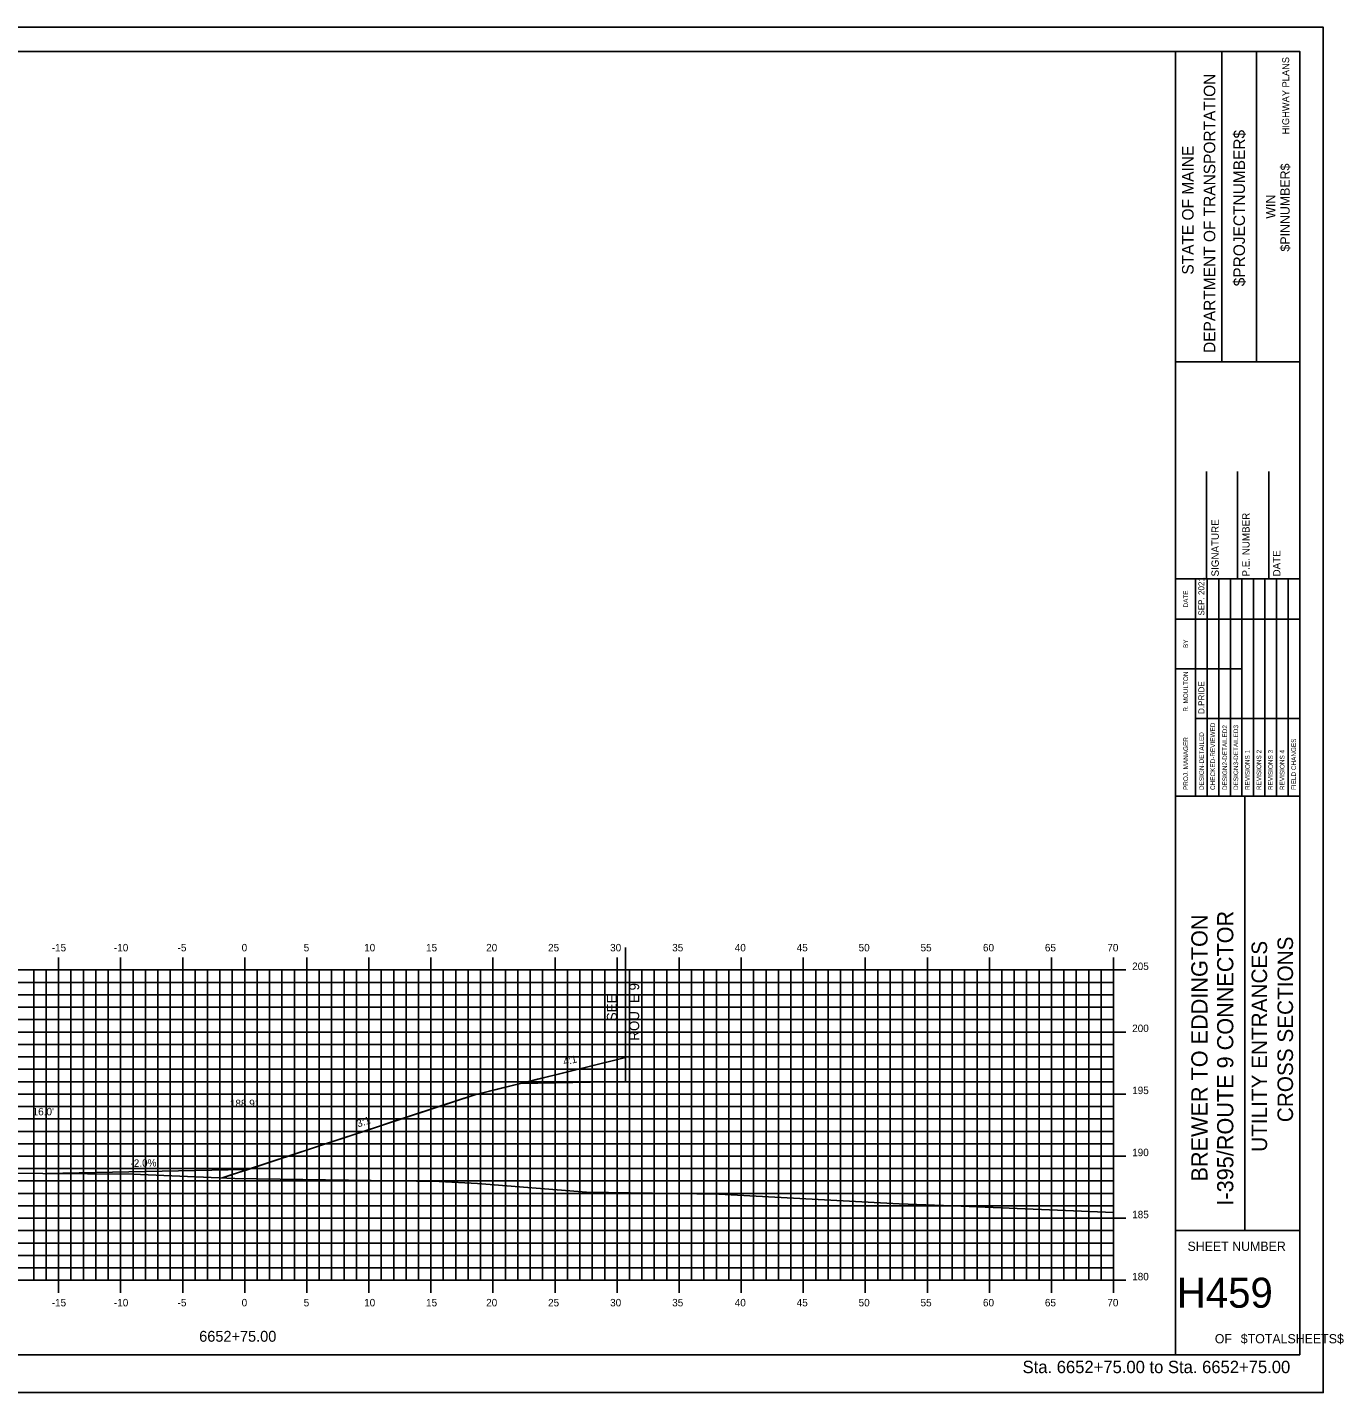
# Model space of a CAD drawing. Extents: x 1724208 to 1724380, y 458501 to 458611.
# Drawn here: x 1724273.5 to 1724379.6, y 458501.2 to 458611.2 of the extents above; entities that cross this region are included whole.
import ezdxf

# ---------------------------------------------------------------- set-up
doc = ezdxf.new("R2010")
doc.units = 0
for name, color, linetype in [('ANNOTATION', 7, 'Continuous'), ('BORDER', 7, 'Continuous'), ('D_Roadway_Centerline', 7, 'Continuous'), ('D_Roadway_Centerline_Text', 7, 'Continuous'), ('D_Roadway_Drive_Gravel', 7, 'Continuous'), ('D_Roadway_Edge_Shoulder', 7, 'Continuous'), ('D_Roadway_SlopeLines', 7, 'Continuous'), ('D_Roadway_SubGrade', 7, 'Continuous'), ('D_Text_Standard', 7, 'Continuous'), ('H_V ANNOTATION', 7, 'Continuous'), ('HIGHWAY_TITLE', 7, 'Continuous'), ('MAJOR', 7, 'Continuous'), ('MINOR', 7, 'Continuous'), ('PLOT BOUNDARY', 7, 'Continuous'), ('S_Roadway_Centerline', 7, 'Continuous')]:
    doc.layers.add(name, color=color, linetype=linetype)

msp = doc.modelspace()

# ---------------------------------------------------------------- linework, layer by layer
at = {"layer": 'BORDER'}
for p, q in [((1724366.06, 458504.25), (1724366.06, 458609.25)), ((1724369.78, 458584.25), (1724369.78, 458609.25)), ((1724372.58, 458584.25), (1724372.58, 458609.25)), ((1724366.06, 458584.25), (1724376.06, 458584.25)), ((1724368.56, 458566.76), (1724368.56, 458575.4)), ((1724371.06, 458566.76), (1724371.06, 458575.4)), ((1724373.56, 458566.76), (1724373.56, 458575.4)), ((1724366.06, 458566.76), (1724376.06, 458566.76)), ((1724366.06, 458549.26), (1724376.06, 458549.26)), ((1724371.65, 458514.26), (1724371.65, 458549.26)), ((1724366.06, 458514.26), (1724376.06, 458514.26))]:
    msp.add_line(p, q, dxfattribs=at)
msp.add_lwpolyline([(1724216.06, 458504.25), (1724376.06, 458504.25), (1724376.06, 458609.25), (1724216.06, 458609.25)], close=True, dxfattribs=at)
for points in [[(1724367.67, 458563.51), (1724367.67, 458566.76)], [(1724367.67, 458549.26), (1724367.67, 458566.05)], [(1724368.6, 458549.26), (1724368.6, 458566.76)], [(1724369.53, 458566.76), (1724369.53, 458549.26)], [(1724370.47, 458549.26), (1724370.47, 458566.76)], [(1724371.4, 458549.26), (1724371.4, 458566.76)], [(1724372.33, 458549.26), (1724372.33, 458566.76)], [(1724373.26, 458549.26), (1724373.26, 458566.76)], [(1724374.19, 458549.26), (1724374.19, 458566.76)], [(1724375.12, 458549.26), (1724375.12, 458566.76)], [(1724366.06, 458563.51), (1724376.06, 458563.51)], [(1724366.06, 458559.51), (1724367.67, 458559.51)], [(1724367.67, 458559.51), (1724371.4, 458559.51)], [(1724367.67, 458555.51), (1724376.06, 458555.51)]]:
    msp.add_lwpolyline(points, dxfattribs=at)
at = {"layer": 'D_Roadway_Centerline'}
msp.add_lwpolyline([(1724289.25, 458518.5), (1724290.01, 458518.75), (1724290.06, 458518.77), (1724291.26, 458519.16), (1724291.97, 458519.4), (1724296.51, 458520.89), (1724297.56, 458521.24), (1724299.06, 458521.73), (1724301.43, 458522.51), (1724303.02, 458523.03), (1724306.22, 458524.09), (1724306.85, 458524.3), (1724309.5, 458525.17), (1724309.52, 458525.17), (1724309.6, 458525.2), (1724311.71, 458525.72), (1724313.28, 458526.11), (1724314.13, 458526.32), (1724314.65, 458526.45), (1724315.64, 458526.69), (1724316.02, 458526.78), (1724318.49, 458527.39), (1724321.74, 458528.2)], dxfattribs=at)
at = {"layer": 'D_Roadway_Drive_Gravel'}
msp.add_lwpolyline([(1724291.06, 458519.17), (1724283.06, 458519.01), (1724275.06, 458518.85), (1724275.03, 458518.84)], dxfattribs=at)
at = {"layer": 'D_Roadway_Edge_Shoulder'}
msp.add_line((1724321.74, 458528.2), (1724321.74, 458527.95), dxfattribs=at)
msp.add_line((1724321.74, 458528.2), (1724321.74, 458527.95), dxfattribs=at)
at = {"layer": 'D_Roadway_SlopeLines'}
for points in [[(1724321.74, 458528.2), (1724309.6, 458525.2), (1724289.25, 458518.5)], [(1724321.74, 458528.2), (1724309.6, 458525.2), (1724289.25, 458518.5)], [(1724321.74, 458528.2), (1724309.6, 458525.2), (1724289.25, 458518.5)], [(1724321.74, 458528.2), (1724309.6, 458525.2), (1724289.25, 458518.5)], [(1724321.74, 458528.2), (1724309.6, 458525.2), (1724289.25, 458518.5)], [(1724321.74, 458528.2), (1724309.6, 458525.2), (1724289.25, 458518.5)], [(1724321.74, 458528.2), (1724309.6, 458525.2)], [(1724321.74, 458528.2), (1724309.6, 458525.2)], [(1724321.74, 458528.2), (1724313.28, 458526.11)], [(1724275.06, 458518.85), (1724275.03, 458518.84)], [(1724291.06, 458519.17), (1724291.28, 458519.17)]]:
    msp.add_lwpolyline(points, dxfattribs=at)
at = {"layer": 'D_Roadway_SubGrade'}
msp.add_line((1724321.74, 458537.06), (1724321.74, 458526.27), dxfattribs=at)
for points in [[(1724321.74, 458526.27), (1724313.28, 458526.11), (1724321.74, 458528.2), (1724321.74, 458527.95)], [(1724321.74, 458527.95), (1724321.74, 458528.2), (1724313.28, 458526.11), (1724321.74, 458526.27)]]:
    msp.add_lwpolyline(points, dxfattribs=at)
at = {"layer": 'MAJOR'}
for p, q in [((1724276.06, 458536.26), (1724276.06, 458535.25)), ((1724281.06, 458536.26), (1724281.06, 458535.25)), ((1724286.06, 458536.26), (1724286.06, 458535.25)), ((1724291.06, 458536.26), (1724291.06, 458535.25)), ((1724296.06, 458536.26), (1724296.06, 458535.25)), ((1724301.06, 458536.26), (1724301.06, 458535.25)), ((1724306.06, 458536.26), (1724306.06, 458535.25)), ((1724311.06, 458536.26), (1724311.06, 458535.25)), ((1724316.06, 458536.26), (1724316.06, 458535.25)), ((1724321.06, 458536.26), (1724321.06, 458535.25)), ((1724326.06, 458536.26), (1724326.06, 458535.25)), ((1724331.06, 458536.26), (1724331.06, 458535.25)), ((1724336.06, 458536.26), (1724336.06, 458535.25)), ((1724341.06, 458536.26), (1724341.06, 458535.25)), ((1724346.06, 458536.26), (1724346.06, 458535.25)), ((1724351.06, 458536.26), (1724351.06, 458535.25)), ((1724356.06, 458536.26), (1724356.06, 458535.25)), ((1724361.06, 458536.26), (1724361.06, 458535.25)), ((1724221.06, 458535.25), (1724361.06, 458535.25)), ((1724221.06, 458535.25), (1724361.06, 458535.25)), ((1724276.06, 458510.25), (1724276.06, 458535.25)), ((1724281.06, 458510.25), (1724281.06, 458535.25)), ((1724286.06, 458510.25), (1724286.06, 458535.25)), ((1724291.06, 458510.25), (1724291.06, 458535.25)), ((1724296.06, 458510.25), (1724296.06, 458535.25)), ((1724301.06, 458510.25), (1724301.06, 458535.25)), ((1724306.06, 458510.25), (1724306.06, 458535.25)), ((1724311.06, 458510.25), (1724311.06, 458535.25)), ((1724316.06, 458510.25), (1724316.06, 458535.25)), ((1724321.06, 458510.25), (1724321.06, 458535.25)), ((1724326.06, 458510.25), (1724326.06, 458535.25)), ((1724331.06, 458510.25), (1724331.06, 458535.25)), ((1724336.06, 458510.25), (1724336.06, 458535.25)), ((1724341.06, 458510.25), (1724341.06, 458535.25)), ((1724346.06, 458510.25), (1724346.06, 458535.25)), ((1724351.06, 458510.25), (1724351.06, 458535.25)), ((1724356.06, 458510.25), (1724356.06, 458535.25)), ((1724362.06, 458535.25), (1724360.05, 458535.25)), ((1724361.06, 458510.25), (1724361.06, 458535.25)), ((1724361.06, 458510.25), (1724361.06, 458535.25)), ((1724221.06, 458530.25), (1724361.06, 458530.25)), ((1724362.06, 458530.25), (1724360.05, 458530.25)), ((1724221.06, 458525.25), (1724361.06, 458525.25)), ((1724362.06, 458525.25), (1724360.05, 458525.25)), ((1724221.06, 458520.25), (1724361.06, 458520.25)), ((1724362.06, 458520.25), (1724360.05, 458520.25)), ((1724221.06, 458515.25), (1724361.06, 458515.25)), ((1724362.06, 458515.25), (1724360.05, 458515.25)), ((1724221.06, 458510.25), (1724361.06, 458510.25)), ((1724221.06, 458510.25), (1724361.06, 458510.25)), ((1724276.06, 458509.25), (1724276.06, 458510.25)), ((1724281.06, 458509.25), (1724281.06, 458510.25)), ((1724286.06, 458509.25), (1724286.06, 458510.25)), ((1724291.06, 458509.25), (1724291.06, 458510.25)), ((1724296.06, 458509.25), (1724296.06, 458510.25)), ((1724301.06, 458509.25), (1724301.06, 458510.25)), ((1724306.06, 458509.25), (1724306.06, 458510.25)), ((1724311.06, 458509.25), (1724311.06, 458510.25)), ((1724316.06, 458509.25), (1724316.06, 458510.25)), ((1724321.06, 458509.25), (1724321.06, 458510.25)), ((1724326.06, 458509.25), (1724326.06, 458510.25)), ((1724331.06, 458509.25), (1724331.06, 458510.25)), ((1724336.06, 458509.25), (1724336.06, 458510.25)), ((1724341.06, 458509.25), (1724341.06, 458510.25)), ((1724346.06, 458509.25), (1724346.06, 458510.25)), ((1724351.06, 458509.25), (1724351.06, 458510.25)), ((1724356.06, 458509.25), (1724356.06, 458510.25)), ((1724362.06, 458510.25), (1724360.05, 458510.25)), ((1724361.06, 458509.25), (1724361.06, 458510.25))]:
    msp.add_line(p, q, dxfattribs=at)
at = {"layer": 'MINOR'}
for p, q in [((1724274.06, 458510.25), (1724274.06, 458535.25)), ((1724275.06, 458510.25), (1724275.06, 458535.25)), ((1724277.06, 458510.25), (1724277.06, 458535.25)), ((1724278.06, 458510.25), (1724278.06, 458535.25)), ((1724279.06, 458510.25), (1724279.06, 458535.25)), ((1724280.06, 458510.25), (1724280.06, 458535.25)), ((1724282.06, 458510.25), (1724282.06, 458535.25)), ((1724283.06, 458510.25), (1724283.06, 458535.25)), ((1724284.06, 458510.25), (1724284.06, 458535.25)), ((1724285.06, 458510.25), (1724285.06, 458535.25)), ((1724287.06, 458510.25), (1724287.06, 458535.25)), ((1724288.06, 458510.25), (1724288.06, 458535.25)), ((1724289.06, 458510.25), (1724289.06, 458535.25)), ((1724290.06, 458510.25), (1724290.06, 458535.25)), ((1724292.06, 458510.25), (1724292.06, 458535.25)), ((1724293.06, 458510.25), (1724293.06, 458535.25)), ((1724294.06, 458510.25), (1724294.06, 458535.25)), ((1724295.06, 458510.25), (1724295.06, 458535.25)), ((1724297.06, 458510.25), (1724297.06, 458535.25)), ((1724298.06, 458510.25), (1724298.06, 458535.25)), ((1724299.06, 458510.25), (1724299.06, 458535.25)), ((1724300.06, 458510.25), (1724300.06, 458535.25)), ((1724302.06, 458510.25), (1724302.06, 458535.25)), ((1724303.06, 458510.25), (1724303.06, 458535.25)), ((1724304.06, 458510.25), (1724304.06, 458535.25)), ((1724305.06, 458510.25), (1724305.06, 458535.25)), ((1724307.06, 458510.25), (1724307.06, 458535.25)), ((1724308.06, 458510.25), (1724308.06, 458535.25)), ((1724309.06, 458510.25), (1724309.06, 458535.25)), ((1724310.06, 458510.25), (1724310.06, 458535.25)), ((1724312.06, 458510.25), (1724312.06, 458535.25)), ((1724313.06, 458510.25), (1724313.06, 458535.25)), ((1724314.06, 458510.25), (1724314.06, 458535.25)), ((1724315.06, 458510.25), (1724315.06, 458535.25)), ((1724317.06, 458510.25), (1724317.06, 458535.25)), ((1724318.06, 458510.25), (1724318.06, 458535.25)), ((1724319.06, 458510.25), (1724319.06, 458535.25)), ((1724320.06, 458510.25), (1724320.06, 458535.25)), ((1724322.06, 458510.25), (1724322.06, 458535.25)), ((1724323.06, 458510.25), (1724323.06, 458535.25)), ((1724324.06, 458510.25), (1724324.06, 458535.25)), ((1724325.06, 458510.25), (1724325.06, 458535.25)), ((1724327.06, 458510.25), (1724327.06, 458535.25)), ((1724328.06, 458510.25), (1724328.06, 458535.25)), ((1724329.06, 458510.25), (1724329.06, 458535.25)), ((1724330.06, 458510.25), (1724330.06, 458535.25)), ((1724332.06, 458510.25), (1724332.06, 458535.25)), ((1724333.06, 458510.25), (1724333.06, 458535.25)), ((1724334.06, 458510.25), (1724334.06, 458535.25)), ((1724335.06, 458510.25), (1724335.06, 458535.25)), ((1724337.06, 458510.25), (1724337.06, 458535.25)), ((1724338.06, 458510.25), (1724338.06, 458535.25)), ((1724339.06, 458510.25), (1724339.06, 458535.25)), ((1724340.06, 458510.25), (1724340.06, 458535.25)), ((1724342.06, 458510.25), (1724342.06, 458535.25)), ((1724343.06, 458510.25), (1724343.06, 458535.25)), ((1724344.06, 458510.25), (1724344.06, 458535.25)), ((1724345.06, 458510.25), (1724345.06, 458535.25)), ((1724347.06, 458510.25), (1724347.06, 458535.25)), ((1724348.06, 458510.25), (1724348.06, 458535.25)), ((1724349.06, 458510.25), (1724349.06, 458535.25)), ((1724350.06, 458510.25), (1724350.06, 458535.25)), ((1724352.06, 458510.25), (1724352.06, 458535.25)), ((1724353.06, 458510.25), (1724353.06, 458535.25)), ((1724354.06, 458510.25), (1724354.06, 458535.25)), ((1724355.06, 458510.25), (1724355.06, 458535.25)), ((1724357.06, 458510.25), (1724357.06, 458535.25)), ((1724358.06, 458510.25), (1724358.06, 458535.25)), ((1724359.06, 458510.25), (1724359.06, 458535.25)), ((1724360.06, 458510.25), (1724360.06, 458535.25)), ((1724221.06, 458534.25), (1724361.06, 458534.25)), ((1724361.06, 458534.25), (1724360.05, 458534.25)), ((1724221.06, 458533.25), (1724361.06, 458533.25)), ((1724361.06, 458533.25), (1724360.05, 458533.25)), ((1724221.06, 458532.25), (1724361.06, 458532.25)), ((1724361.06, 458532.25), (1724360.05, 458532.25)), ((1724221.06, 458531.25), (1724361.06, 458531.25)), ((1724361.06, 458531.25), (1724360.05, 458531.25)), ((1724221.06, 458529.25), (1724361.06, 458529.25)), ((1724361.06, 458529.25), (1724360.05, 458529.25)), ((1724221.06, 458528.25), (1724361.06, 458528.25)), ((1724361.06, 458528.25), (1724360.05, 458528.25)), ((1724221.06, 458527.25), (1724361.06, 458527.25)), ((1724221.06, 458526.25), (1724361.06, 458526.25)), ((1724361.06, 458527.25), (1724360.05, 458527.25)), ((1724361.06, 458526.25), (1724360.05, 458526.25)), ((1724221.06, 458524.25), (1724361.06, 458524.25)), ((1724361.06, 458524.25), (1724360.05, 458524.25)), ((1724221.06, 458523.25), (1724361.06, 458523.25)), ((1724361.06, 458523.25), (1724360.05, 458523.25)), ((1724221.06, 458522.25), (1724361.06, 458522.25)), ((1724361.06, 458522.25), (1724360.05, 458522.25)), ((1724221.06, 458521.25), (1724361.06, 458521.25)), ((1724361.06, 458521.25), (1724360.05, 458521.25)), ((1724221.06, 458519.25), (1724361.06, 458519.25)), ((1724361.06, 458519.25), (1724360.05, 458519.25)), ((1724221.06, 458518.25), (1724361.06, 458518.25)), ((1724361.06, 458518.25), (1724360.05, 458518.25)), ((1724221.06, 458517.25), (1724361.06, 458517.25)), ((1724361.06, 458517.25), (1724360.05, 458517.25)), ((1724221.06, 458516.25), (1724361.06, 458516.25)), ((1724361.06, 458516.25), (1724360.05, 458516.25)), ((1724221.06, 458514.25), (1724361.06, 458514.25)), ((1724361.06, 458514.25), (1724360.05, 458514.25)), ((1724221.06, 458513.25), (1724361.06, 458513.25)), ((1724361.06, 458513.25), (1724360.05, 458513.25)), ((1724221.06, 458512.25), (1724361.06, 458512.25)), ((1724361.06, 458512.25), (1724360.05, 458512.25)), ((1724221.06, 458511.25), (1724361.06, 458511.25)), ((1724361.06, 458511.25), (1724360.05, 458511.25))]:
    msp.add_line(p, q, dxfattribs=at)
at = {"layer": 'PLOT BOUNDARY'}
msp.add_lwpolyline([(1724207.96, 458501.2), (1724377.96, 458501.2), (1724377.96, 458611.2), (1724207.96, 458611.2)], close=True, dxfattribs=at)
at = {"layer": 'S_Roadway_Centerline'}
msp.add_lwpolyline([(1724221.06, 458519.86), (1724222.04, 458519.84), (1724233.13, 458519.69), (1724237.5, 458519.63), (1724246.58, 458519.43), (1724252.36, 458519.21), (1724258.45, 458519.37), (1724270.48, 458518.9), (1724271.14, 458518.87), (1724282.01, 458518.79), (1724290.27, 458518.46), (1724306.73, 458518.2), (1724309.81, 458518.04), (1724318.6, 458517.35), (1724329.26, 458517.2), (1724343.8, 458516.42), (1724348.79, 458516.23), (1724361.06, 458515.7)], dxfattribs=at)

# ---------------------------------------------------------------- texts
at = {"layer": 'ANNOTATION'}
for s, height, rotation, p in [('ROUTE 9', 0.8, 90, (1724322.84, 458529.56)), ('SEE', 0.8, 90, (1724321.04, 458531.13)), ('4:1', 0.6, 13.6162, (1724316.79, 458527.55)), ('3:1', 0.6, 18.4349, (1724300.19, 458522.56)), ('-2.0%', 0.6, 1.1458, (1724281.86, 458519.38))]:
    msp.add_text(s, height=height, rotation=rotation, dxfattribs=at).set_placement(p)
at = {"layer": 'BORDER'}
for s, height, p in [('DEPARTMENT OF TRANSPORTATION', 0.9318, (1724369.26, 458584.96)), ('$PROJECTNUMBER$', 0.9318, (1724371.65, 458590.33)), ('STATE OF MAINE', 0.9318, (1724367.51, 458591.27)), ('$PINNUMBER$', 0.7453, (1724375.25, 458593.13)), ('WIN', 0.745, (1724374.09, 458595.78)), ('SIGNATURE', 0.591, (1724369.54, 458566.95)), ('P.E. NUMBER', 0.5906, (1724372.02, 458566.95)), ('DATE', 0.591, (1724374.5, 458566.95)), ('SEP. 2021', 0.485, (1724368.38, 458563.8)), ('DATE', 0.371, (1724367.06, 458564.46)), ('BY', 0.371, (1724367.06, 458561.19)), ('R. MOULTON', 0.373, (1724367.06, 458556.06)), ('D.PRIDE', 0.485, (1724368.38, 458555.88)), ('CHECKED-REVIEWED', 0.3727, (1724369.24, 458549.75)), ('PROJ. MANAGER', 0.3727, (1724367.06, 458549.75)), ('DESIGN-DETAILED', 0.3727, (1724368.34, 458549.75)), ('DESIGN2-DETAILED2', 0.3727, (1724370.21, 458549.75)), ('DESIGN3-DETAILED3', 0.3727, (1724371.1, 458549.75)), ('FIELD CHANGES', 0.3727, (1724375.76, 458549.75)), ('REVISIONS 1', 0.3727, (1724372.03, 458549.75)), ('REVISIONS 2', 0.3727, (1724372.96, 458549.75)), ('REVISIONS 3', 0.3727, (1724373.89, 458549.75)), ('REVISIONS 4', 0.3727, (1724374.83, 458549.75)), ('UTILITY ENTRANCES', 1.25, (1724373.43, 458520.6)), ('CROSS SECTIONS', 1.25, (1724375.52, 458522.99))]:
    msp.add_text(s, height=height, rotation=90, dxfattribs=at).set_placement(p)
for s, height, p in [('SHEET NUMBER', 0.7453, (1724367.02, 458512.62)), ('H459', 2.419, (1724366.16, 458508.04)), ('OF', 0.745, (1724369.22, 458505.17)), ('$TOTALSHEETS$', 0.7453, (1724371.31, 458505.17))]:
    msp.add_text(s, height=height, dxfattribs=at).set_placement(p)
at = {"layer": 'D_Roadway_Centerline_Text'}
msp.add_text('188.91', height=0.6, dxfattribs=at).set_placement((1724289.86, 458524.2))
at = {"layer": 'D_Text_Standard'}
msp.add_text("16.0'", height=0.6, dxfattribs=at).set_placement((1724273.97, 458523.54))
at = {"layer": 'H_V ANNOTATION'}
for s, height, p in [('-15', 0.6, (1724275.51, 458536.75)), ('-10', 0.6, (1724280.52, 458536.75)), ('-5', 0.6, (1724285.65, 458536.75)), ('0', 0.6, (1724290.81, 458536.75)), ('5', 0.6, (1724295.81, 458536.75)), ('10', 0.6, (1724300.68, 458536.75)), ('15', 0.6, (1724305.67, 458536.75)), ('20', 0.6, (1724310.51, 458536.75)), ('25', 0.6, (1724315.5, 458536.75)), ('30', 0.6, (1724320.5, 458536.75)), ('35', 0.6, (1724325.5, 458536.75)), ('40', 0.6, (1724330.54, 458536.75)), ('45', 0.6, (1724335.53, 458536.75)), ('50', 0.6, (1724340.52, 458536.75)), ('55', 0.6, (1724345.51, 458536.75)), ('60', 0.6, (1724350.54, 458536.75)), ('65', 0.6, (1724355.53, 458536.75)), ('70', 0.6, (1724360.56, 458536.75)), ('205', 0.6, (1724362.56, 458535.25)), ('200', 0.6, (1724362.56, 458530.25)), ('195', 0.6, (1724362.56, 458525.25)), ('190', 0.6, (1724362.56, 458520.25)), ('185', 0.6, (1724362.56, 458515.25)), ('180', 0.6, (1724362.56, 458510.25)), ('-15', 0.6, (1724275.51, 458508.15)), ('-10', 0.6, (1724280.52, 458508.15)), ('-5', 0.6, (1724285.65, 458508.15)), ('0', 0.6, (1724290.81, 458508.15)), ('5', 0.6, (1724295.81, 458508.15)), ('10', 0.6, (1724300.68, 458508.15)), ('15', 0.6, (1724305.67, 458508.15)), ('20', 0.6, (1724310.51, 458508.15)), ('25', 0.6, (1724315.5, 458508.15)), ('30', 0.6, (1724320.5, 458508.15)), ('35', 0.6, (1724325.5, 458508.15)), ('40', 0.6, (1724330.54, 458508.15)), ('45', 0.6, (1724335.53, 458508.15)), ('50', 0.6, (1724340.52, 458508.15)), ('55', 0.6, (1724345.51, 458508.15)), ('60', 0.6, (1724350.54, 458508.15)), ('65', 0.6, (1724355.53, 458508.15)), ('70', 0.6, (1724360.56, 458508.15)), ('6652+75.00', 0.875, (1724287.39, 458505.3)), ('Sta. 6652+75.00 to Sta. 6652+75.00', 1.0002, (1724353.73, 458502.77))]:
    msp.add_text(s, height=height, dxfattribs=at).set_placement(p)
at = {"layer": 'HIGHWAY_TITLE'}
for s, height, p in [('HIGHWAY PLANS', 0.559, (1724375.21, 458602.57)), ('BREWER TO EDDINGTON', 1.3043, (1724368.63, 458518.21)), ('I-395/ROUTE 9 CONNECTOR', 1.3043, (1724370.71, 458516.27))]:
    msp.add_text(s, height=height, rotation=90, dxfattribs=at).set_placement(p)

doc.saveas('drawing.dxf')
